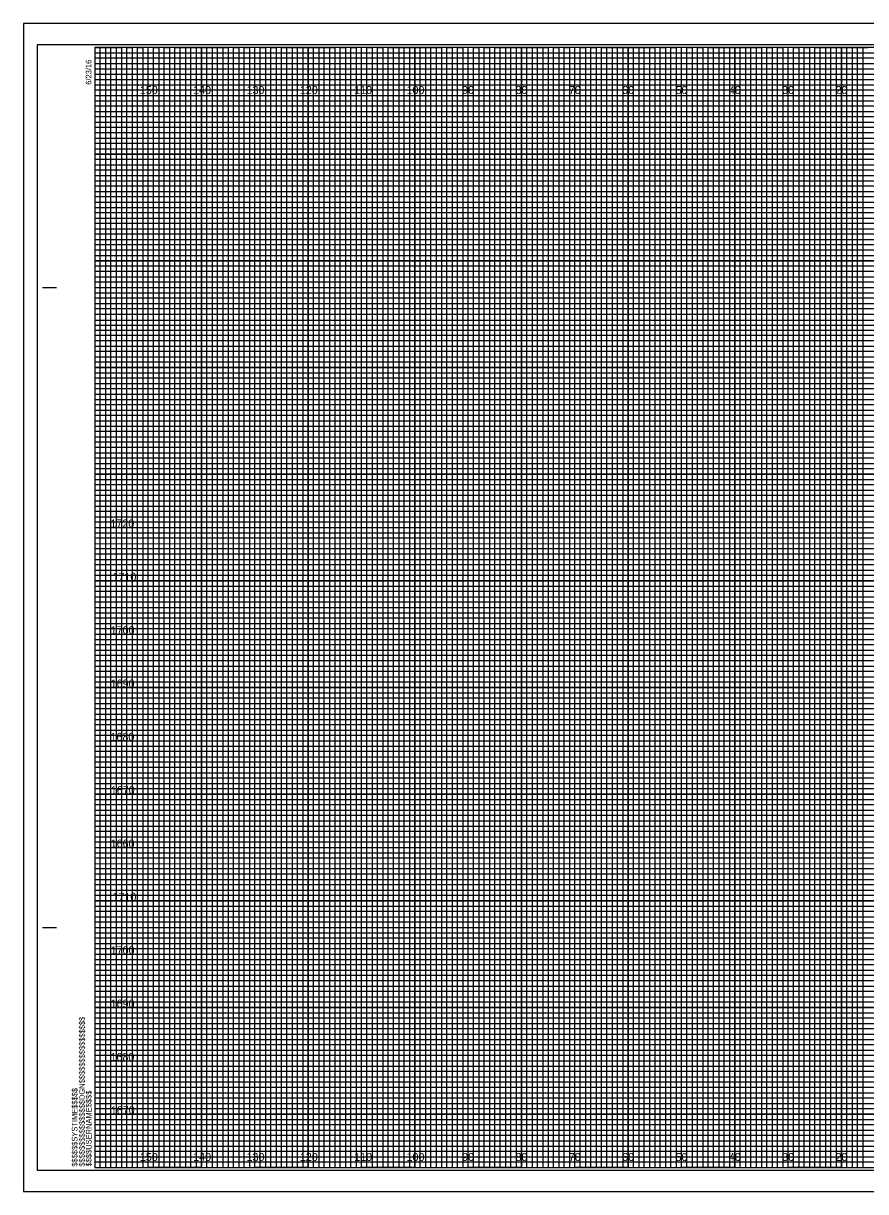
# Model space of a CAD drawing. Extents: x 656 to 993, y -2 to 2857.
# Drawn here: x 656.3 to 814.2, y -1.7 to 217.3 of the extents above; entities that cross this region are included whole.
import ezdxf

# ---------------------------------------------------------------- set-up
doc = ezdxf.new("R2010")
doc.units = 0
for name, color, linetype in [('Prop RDY Alternate Text Blue', 7, 'Continuous'), ('Prop Retaining Wall', 7, 'Continuous'), ('Prop SS Cut Line', 7, 'Continuous'), ('Prop SS Fill Line', 7, 'Continuous'), ('Prop SS Transition Line', 7, 'Continuous'), ('Raster_Level_0', 7, 'Continuous'), ('Raster_Level_3', 7, 'Continuous'), ('Scratch_Level_3', 7, 'Continuous'), ('Scratch_Level_7', 7, 'Continuous'), ('Typical Guardrail CELL', 7, 'Continuous'), ('Typical Text Asphalt at Bridge Approach CELL', 7, 'Continuous')]:
    doc.layers.add(name, color=color, linetype=linetype)

msp = doc.modelspace()

# ---------------------------------------------------------------- linework, layer by layer
at = {"layer": 'Prop RDY Alternate Text Blue'}
for p, q in [((679.74, 2.8), (679.74, 212.8)), ((689.74, 2.8), (689.74, 212.8)), ((699.74, 2.8), (699.74, 212.8)), ((709.74, 2.8), (709.74, 212.8)), ((719.74, 2.8), (719.74, 212.8)), ((729.74, 2.8), (729.74, 212.8)), ((739.74, 2.8), (739.74, 212.8)), ((749.74, 2.8), (749.74, 212.8)), ((759.74, 2.8), (759.74, 212.8)), ((769.74, 2.8), (769.74, 212.8)), ((779.74, 2.8), (779.74, 212.8)), ((789.74, 2.8), (789.74, 212.8)), ((799.74, 2.8), (799.74, 212.8)), ((809.74, 2.8), (809.74, 212.8)), ((669.74, 202.8), (989.74, 202.8)), ((669.74, 192.8), (989.74, 192.8)), ((669.74, 182.8), (989.74, 182.8)), ((669.74, 172.8), (989.74, 172.8)), ((669.74, 162.8), (989.74, 162.8)), ((669.74, 152.8), (989.74, 152.8)), ((669.74, 142.8), (989.74, 142.8)), ((669.74, 132.8), (989.74, 132.8)), ((669.74, 122.8), (989.74, 122.8)), ((669.74, 112.8), (989.74, 112.8)), ((669.74, 102.8), (989.74, 102.8)), ((669.74, 92.8), (989.74, 92.8)), ((669.74, 82.8), (989.74, 82.8)), ((669.74, 72.8), (989.74, 72.8)), ((669.74, 62.8), (989.74, 62.8)), ((669.74, 52.8), (989.74, 52.8)), ((669.74, 42.8), (989.74, 42.8)), ((669.74, 32.8), (989.74, 32.8)), ((669.74, 22.8), (989.74, 22.8)), ((669.74, 12.8), (989.74, 12.8))]:
    msp.add_line(p, q, dxfattribs=at)
at = {"layer": 'Prop Retaining Wall'}
for p, q in [((659.94, 167.8), (662.44, 167.8)), ((660.04, 167.8), (662.54, 167.8)), ((659.94, 47.8), (662.44, 47.8)), ((660.04, 47.8), (662.54, 47.8)), ((669.74, 2.8), (669.74, 2.8)), ((669.74, 2.8), (669.74, 2.8)), ((669.74, 2.8), (669.74, 2.8)), ((669.74, 2.8), (669.74, 2.8)), ((669.74, 2.8), (669.74, 2.8)), ((669.74, 2.8), (669.74, 2.8)), ((669.74, 2.8), (669.74, 2.8))]:
    msp.add_line(p, q, dxfattribs=at)
msp.add_lwpolyline([(989.74, 212.8), (669.74, 212.8), (669.74, 2.8), (989.74, 2.8)], close=True, dxfattribs=at)
at = {"layer": 'Prop SS Cut Line'}
for points in [[(669.74, 212.8), (674.74, 212.8), (674.74, 2.8), (684.74, 2.8), (684.74, 212.8), (694.74, 212.8), (694.74, 2.8), (704.74, 2.8), (704.74, 212.8), (714.74, 212.8), (714.74, 2.8), (724.74, 2.8), (724.74, 212.8), (734.74, 212.8), (734.74, 2.8), (744.74, 2.8), (744.74, 212.8), (754.74, 212.8), (754.74, 2.8), (764.74, 2.8), (764.74, 212.8), (774.74, 212.8), (774.74, 2.8), (784.74, 2.8), (784.74, 212.8), (794.74, 212.8), (794.74, 2.8), (804.74, 2.8), (804.74, 212.8), (814.74, 212.8)], [(669.74, 207.8), (944.74, 207.8)], [(669.74, 187.8), (989.74, 187.8), (989.74, 197.8), (669.74, 197.8)], [(669.74, 167.8), (989.74, 167.8), (989.74, 177.8), (669.74, 177.8)], [(669.74, 147.8), (989.74, 147.8), (989.74, 157.8), (669.74, 157.8)], [(669.74, 127.8), (989.74, 127.8), (989.74, 137.8), (669.74, 137.8)], [(669.74, 107.8), (989.74, 107.8), (989.74, 117.8), (669.74, 117.8)], [(669.74, 87.8), (989.74, 87.8), (989.74, 97.8), (669.74, 97.8)], [(669.74, 67.8), (989.74, 67.8), (989.74, 77.8), (669.74, 77.8)], [(669.74, 47.8), (989.74, 47.8), (989.74, 57.8), (669.74, 57.8)], [(669.74, 27.8), (989.74, 27.8), (989.74, 37.8), (669.74, 37.8)], [(669.74, 7.8), (989.74, 7.8), (989.74, 17.8), (669.74, 17.8)]]:
    msp.add_lwpolyline(points, dxfattribs=at)
at = {"layer": 'Prop SS Fill Line'}
for p, q in [((679.74, 212.8), (669.74, 212.8)), ((679.74, 2.8), (679.74, 212.8)), ((699.74, 212.8), (689.74, 212.8)), ((689.74, 212.8), (689.74, 2.8)), ((699.74, 2.8), (699.74, 212.8)), ((719.74, 212.8), (709.74, 212.8)), ((709.74, 212.8), (709.74, 2.8)), ((719.74, 2.8), (719.74, 212.8)), ((739.74, 212.8), (729.74, 212.8)), ((729.74, 212.8), (729.74, 2.8)), ((739.74, 2.8), (739.74, 212.8)), ((759.74, 212.8), (749.74, 212.8)), ((749.74, 212.8), (749.74, 2.8)), ((759.74, 2.8), (759.74, 212.8)), ((779.74, 212.8), (769.74, 212.8)), ((769.74, 212.8), (769.74, 2.8)), ((779.74, 2.8), (779.74, 212.8)), ((799.74, 212.8), (789.74, 212.8)), ((789.74, 212.8), (789.74, 2.8)), ((799.74, 2.8), (799.74, 212.8)), ((819.74, 212.8), (809.74, 212.8)), ((809.74, 212.8), (809.74, 2.8)), ((689.74, 2.8), (679.74, 2.8)), ((709.74, 2.8), (699.74, 2.8)), ((729.74, 2.8), (719.74, 2.8)), ((749.74, 2.8), (739.74, 2.8)), ((769.74, 2.8), (759.74, 2.8)), ((789.74, 2.8), (779.74, 2.8)), ((809.74, 2.8), (799.74, 2.8))]:
    msp.add_line(p, q, dxfattribs=at)
for points in [[(669.74, 202.8), (989.74, 202.8), (989.74, 192.8), (669.74, 192.8)], [(669.74, 182.8), (989.74, 182.8), (989.74, 172.8), (669.74, 172.8)], [(669.74, 162.8), (989.74, 162.8), (989.74, 152.8), (669.74, 152.8)], [(669.74, 142.8), (989.74, 142.8), (989.74, 132.8), (669.74, 132.8)], [(669.74, 122.8), (989.74, 122.8), (989.74, 112.8), (669.74, 112.8)], [(669.74, 102.8), (989.74, 102.8), (989.74, 92.8), (669.74, 92.8)], [(669.74, 82.8), (989.74, 82.8), (989.74, 72.8), (669.74, 72.8)], [(669.74, 62.8), (989.74, 62.8), (989.74, 52.8), (669.74, 52.8)], [(669.74, 42.8), (989.74, 42.8), (989.74, 32.8), (669.74, 32.8)], [(669.74, 22.8), (989.74, 22.8), (989.74, 12.8), (669.74, 12.8)]]:
    msp.add_lwpolyline(points, dxfattribs=at)
at = {"layer": 'Prop SS Transition Line'}
for p, q in [((669.74, 211.8), (929.74, 211.8)), ((929.74, 210.78), (669.74, 210.78)), ((669.74, 210.78), (669.74, 209.8)), ((669.74, 209.8), (929.74, 209.8)), ((929.74, 208.69), (669.74, 208.69)), ((669.74, 208.69), (669.74, 206.8)), ((669.74, 206.8), (989.74, 206.8))]:
    msp.add_line(p, q, dxfattribs=at)
for points in [[(669.74, 205.8), (939.74, 205.8), (989.74, 205.8), (989.74, 204.8), (669.74, 204.8)], [(669.74, 203.8), (989.74, 203.8), (989.74, 201.8), (669.74, 201.8)], [(669.74, 200.8), (989.74, 200.8), (989.74, 199.8), (669.74, 199.78)], [(669.74, 198.8), (989.74, 198.8), (989.74, 196.8), (669.74, 196.8)], [(669.74, 195.8), (989.74, 195.8), (989.74, 194.8), (669.74, 194.8)], [(669.74, 193.8), (989.74, 193.8), (989.74, 191.8), (669.74, 191.8)], [(669.74, 190.8), (989.74, 190.8), (989.74, 189.8), (669.74, 189.8)], [(669.74, 188.8), (989.74, 188.8), (989.74, 186.8), (669.74, 186.8)], [(669.74, 185.8), (989.74, 185.8), (989.74, 184.8), (669.74, 184.8)], [(669.74, 183.8), (989.74, 183.8), (989.74, 181.8), (669.74, 181.8)], [(669.74, 180.8), (989.74, 180.8), (989.74, 179.8), (669.74, 179.8)], [(669.74, 178.8), (989.74, 178.8), (989.74, 176.75), (989.74, 175.8), (989.74, 174.8), (669.74, 174.8)], [(669.74, 176.8), (989.74, 176.8), (989.74, 175.8), (669.74, 175.8)], [(669.74, 173.8), (989.74, 173.8), (989.74, 171.8), (669.74, 171.83)], [(669.74, 171.83), (989.74, 171.8), (989.74, 170.8), (669.74, 170.8)], [(669.74, 169.8), (989.74, 169.8), (989.74, 168.8), (669.74, 168.8)], [(669.74, 166.8), (989.74, 166.8), (989.74, 165.8), (669.74, 165.8)], [(669.74, 164.8), (989.74, 164.8), (989.74, 163.8), (669.74, 163.8)], [(669.67, 161.69), (989.74, 161.69), (989.74, 160.68), (669.67, 160.68)], [(669.74, 159.8), (989.74, 159.8), (989.74, 158.8), (669.74, 158.8)], [(669.74, 156.8), (989.74, 156.8), (989.74, 155.8), (669.74, 155.8)], [(669.74, 154.8), (989.74, 154.8), (989.74, 153.8), (669.74, 153.8)], [(669.74, 151.8), (989.74, 151.8), (989.74, 150.8), (669.74, 150.8)], [(669.74, 149.8), (989.74, 149.8), (989.74, 148.8), (669.74, 148.8)], [(669.74, 146.8), (989.74, 146.8), (989.74, 145.8), (669.74, 145.8)], [(669.74, 144.8), (989.74, 144.8), (989.74, 143.8), (669.74, 143.8)], [(669.74, 141.8), (989.74, 141.8), (989.73, 140.78), (669.74, 140.8)], [(669.74, 139.8), (989.74, 139.8), (989.74, 138.8), (669.74, 138.8)], [(669.74, 136.8), (989.74, 136.8), (989.74, 135.8), (669.74, 135.8)], [(669.74, 134.8), (989.74, 134.8), (989.74, 133.8), (669.74, 133.8)], [(669.74, 131.8), (989.74, 131.8), (989.74, 130.8), (669.74, 130.8)], [(669.74, 129.8), (989.74, 129.8), (989.74, 128.8), (669.74, 128.8)], [(669.74, 126.8), (989.74, 126.8), (989.74, 125.8), (669.74, 125.8)], [(669.74, 124.8), (989.74, 124.8), (989.74, 123.8), (669.74, 123.8)], [(669.74, 121.8), (989.74, 121.8), (989.74, 120.8), (669.74, 120.8)], [(669.74, 119.79), (989.81, 119.71), (989.74, 118.8), (669.74, 118.8)], [(669.74, 116.8), (989.74, 116.8), (989.74, 115.8), (669.74, 115.8)], [(669.74, 114.8), (989.74, 114.8), (989.74, 113.8), (669.74, 113.8)], [(669.74, 111.8), (989.74, 111.8), (989.74, 110.8), (669.74, 110.8)], [(669.74, 109.8), (989.74, 109.8), (989.74, 108.8), (669.74, 108.8)], [(669.74, 106.8), (989.74, 106.8), (989.74, 105.8), (669.74, 105.8)], [(669.74, 104.8), (989.74, 104.8), (989.74, 103.8), (669.74, 103.8)], [(669.74, 101.8), (989.74, 101.8), (989.74, 100.8), (669.74, 100.8)], [(669.74, 99.8), (989.74, 99.8), (989.74, 98.8), (669.74, 98.8)], [(669.74, 96.8), (989.74, 96.8), (989.74, 95.8), (669.74, 95.8)], [(669.74, 94.8), (989.74, 94.8), (989.74, 93.8), (669.74, 93.8)], [(669.74, 91.8), (989.74, 91.8), (989.74, 90.8), (669.74, 90.8)], [(669.74, 89.8), (989.74, 89.8), (989.74, 88.8), (669.74, 88.8)], [(669.74, 86.8), (989.74, 86.8), (989.74, 85.8), (669.74, 85.8)], [(669.74, 84.8), (989.74, 84.8), (989.74, 83.8), (669.74, 83.8)], [(669.74, 81.8), (989.74, 81.8), (989.73, 80.78), (669.74, 80.8)], [(669.74, 79.8), (989.74, 79.8), (989.74, 78.8), (669.74, 78.8)], [(669.74, 76.8), (989.74, 76.8), (989.74, 75.8), (669.74, 75.8)], [(669.74, 74.8), (989.74, 74.8), (989.74, 73.8), (669.74, 73.8)], [(669.74, 71.8), (989.74, 71.8), (989.74, 70.8), (669.74, 70.8)], [(669.74, 69.8), (989.74, 69.8), (989.74, 68.8), (669.74, 68.8)], [(669.74, 66.8), (989.74, 66.8), (989.74, 65.8), (669.74, 65.8)], [(669.74, 64.8), (989.74, 64.8), (989.74, 63.8), (669.74, 63.8)], [(669.74, 61.8), (989.74, 61.8), (989.74, 60.8), (669.74, 60.8)], [(669.74, 59.79), (989.81, 59.71), (989.74, 58.8), (669.74, 58.8)], [(669.74, 56.8), (989.74, 56.8), (989.74, 55.8), (669.74, 55.8)], [(669.74, 54.8), (989.74, 54.8), (989.74, 53.8), (669.74, 53.8)], [(669.74, 51.8), (989.74, 51.8), (989.74, 50.8), (669.74, 50.8)], [(669.74, 49.8), (989.74, 49.8), (989.74, 48.8), (669.74, 48.8)], [(669.74, 46.8), (989.74, 46.8), (989.74, 45.8), (669.74, 45.8)], [(669.74, 44.8), (989.74, 44.8), (989.74, 43.8), (669.74, 43.8)], [(669.74, 41.8), (989.74, 41.8), (989.74, 40.8), (669.74, 40.8)], [(669.74, 39.8), (989.74, 39.8), (989.74, 38.8), (669.74, 38.8)], [(669.74, 36.8), (989.74, 36.8), (989.74, 35.8), (669.74, 35.8)], [(669.74, 34.8), (989.74, 34.8), (989.74, 33.8), (669.74, 33.8)], [(669.74, 31.8), (989.74, 31.8), (989.74, 30.8), (669.74, 30.8)], [(669.74, 29.8), (989.74, 29.8), (989.74, 28.8), (669.74, 28.8)], [(669.74, 26.8), (989.74, 26.8), (989.74, 25.8), (669.74, 25.8)], [(669.74, 24.8), (989.74, 24.8), (989.74, 23.8), (669.74, 23.8)], [(669.74, 21.8), (989.74, 21.8), (989.74, 20.8), (669.74, 20.8)], [(669.74, 19.8), (989.74, 19.8), (989.74, 18.8), (669.74, 18.8)], [(669.74, 16.8), (989.74, 16.8), (989.74, 15.8), (669.74, 15.8)], [(669.74, 14.8), (989.74, 14.8), (989.74, 13.8), (669.74, 13.8)], [(669.74, 11.8), (989.74, 11.8), (989.74, 10.8), (669.74, 10.8)], [(669.74, 9.8), (989.74, 9.8), (989.74, 8.8), (669.74, 8.8)], [(669.74, 6.8), (989.74, 6.8), (989.74, 5.8), (669.74, 5.8)], [(669.74, 4.8), (989.74, 4.8), (989.74, 3.8), (669.74, 3.8)]]:
    msp.add_lwpolyline(points, dxfattribs=at)
at = {"layer": 'Raster_Level_3'}
for points in [[(669.74, 2.8), (670.74, 2.8), (670.74, 212.8), (671.74, 212.8), (671.74, 2.8)], [(671.74, 2.8), (672.74, 2.8), (672.74, 212.8), (673.74, 212.8), (673.74, 2.8)], [(674.74, 2.8), (675.74, 2.8), (675.74, 212.8), (676.74, 212.8), (676.74, 2.8)], [(676.74, 2.8), (677.74, 2.8), (677.74, 212.8), (678.74, 212.8), (678.74, 2.8)], [(679.74, 2.8), (680.74, 2.8), (680.74, 212.8), (681.74, 212.8), (681.74, 2.8)], [(681.74, 2.8), (682.74, 2.8), (682.74, 212.8), (683.74, 212.8), (683.74, 2.8)], [(684.74, 2.8), (685.74, 2.8), (685.74, 212.8), (686.74, 212.8), (686.74, 2.8)], [(686.74, 2.8), (687.74, 2.8), (687.74, 212.8), (688.74, 212.8), (688.74, 2.8)], [(689.74, 2.8), (690.74, 2.8), (690.74, 212.8), (691.74, 212.8), (691.74, 2.8)], [(691.74, 2.8), (692.74, 2.8), (692.74, 212.8), (693.74, 212.8), (693.74, 2.8)], [(694.74, 2.8), (695.74, 2.8), (695.74, 212.8), (696.74, 212.8), (696.74, 2.8)], [(696.74, 2.8), (697.74, 2.8), (697.74, 212.8), (698.74, 212.8), (698.74, 2.8)], [(699.74, 2.8), (700.74, 2.8), (700.74, 212.8), (701.74, 212.8), (701.74, 2.8)], [(701.74, 2.8), (702.74, 2.8), (702.74, 212.8), (703.74, 212.8), (703.74, 2.8)], [(704.74, 2.8), (705.74, 2.8), (705.74, 212.8), (706.74, 212.8), (706.74, 2.8)], [(706.74, 2.8), (707.74, 2.8), (707.74, 212.8), (708.74, 212.8), (708.74, 2.8)], [(709.74, 2.8), (710.74, 2.8), (710.74, 212.8), (711.74, 212.8), (711.74, 2.8)], [(711.74, 2.8), (712.74, 2.8), (712.74, 212.8), (713.74, 212.8), (713.74, 2.8)], [(714.74, 2.8), (715.74, 2.8), (715.74, 212.8), (716.74, 212.8), (716.74, 2.8)], [(716.74, 2.8), (717.74, 2.8), (717.74, 212.8), (718.74, 212.8), (718.74, 2.8)], [(719.74, 2.8), (720.74, 2.8), (720.74, 212.8), (721.74, 212.8), (721.74, 2.8)], [(721.74, 2.8), (722.74, 2.8), (722.74, 212.8), (723.74, 212.8), (723.74, 2.8)], [(724.74, 2.8), (725.74, 2.8), (725.74, 212.8), (726.74, 212.8), (726.74, 2.8)], [(726.74, 2.8), (727.74, 2.8), (727.74, 212.8), (728.74, 212.8), (728.74, 2.8)], [(729.74, 2.8), (730.74, 2.8), (730.74, 212.8), (731.74, 212.8), (731.74, 2.8)], [(731.74, 2.8), (732.74, 2.8), (732.74, 212.8), (733.74, 212.8), (733.74, 2.8)], [(734.74, 2.8), (735.74, 2.8), (735.74, 212.8), (736.74, 212.8), (736.74, 2.8)], [(736.74, 2.8), (737.74, 2.8), (737.74, 212.8), (738.74, 212.8), (738.74, 2.8)], [(739.74, 2.8), (740.74, 2.8), (740.74, 212.8), (741.74, 212.8), (741.74, 2.8)], [(741.74, 2.8), (742.74, 2.8), (742.74, 212.8), (743.74, 212.8), (743.74, 2.8)], [(744.74, 2.8), (745.74, 2.8), (745.74, 212.8), (746.74, 212.8), (746.74, 2.8)], [(746.74, 2.8), (747.74, 2.8), (747.74, 212.8), (748.74, 212.8), (748.74, 2.8)], [(749.74, 2.8), (750.74, 2.8), (750.74, 212.8), (751.74, 212.8), (751.74, 2.8)], [(751.74, 2.8), (752.74, 2.8), (752.74, 212.8), (753.74, 212.8), (753.74, 2.8)], [(754.74, 2.8), (755.74, 2.8), (755.74, 212.8), (756.74, 212.8), (756.74, 2.8)], [(756.74, 2.8), (757.74, 2.8), (757.74, 212.8), (758.74, 212.8), (758.74, 2.8)], [(759.74, 2.8), (760.74, 2.8), (760.74, 212.8), (761.74, 212.8), (761.74, 2.8)], [(761.74, 2.8), (762.74, 2.8), (762.74, 212.8), (763.74, 212.8), (763.74, 2.8)], [(764.74, 2.8), (765.74, 2.8), (765.74, 212.8), (766.74, 212.8), (766.74, 2.8)], [(766.74, 2.8), (767.74, 2.8), (767.74, 212.8), (768.74, 212.8), (768.74, 2.8)], [(769.74, 2.8), (770.74, 2.8), (770.74, 212.8), (771.74, 212.8), (771.74, 2.8)], [(771.74, 2.8), (772.74, 2.8), (772.74, 212.8), (773.74, 212.8), (773.74, 2.8)], [(774.74, 2.8), (775.74, 2.8), (775.74, 212.8), (776.74, 212.8), (776.74, 2.8)], [(776.74, 2.8), (777.74, 2.8), (777.74, 212.8), (778.74, 212.8), (778.74, 2.8)], [(779.74, 2.8), (780.74, 2.8), (780.74, 212.8), (781.74, 212.8), (781.74, 2.8)], [(781.74, 2.8), (782.74, 2.8), (782.74, 212.8), (783.74, 212.8), (783.74, 2.8)], [(784.74, 2.8), (785.74, 2.8), (785.74, 212.8), (786.74, 212.8), (786.74, 2.8)], [(786.74, 2.8), (787.74, 2.8), (787.74, 212.8), (788.74, 212.8), (788.74, 2.8)], [(789.74, 2.8), (790.74, 2.8), (790.74, 212.8), (791.74, 212.8), (791.74, 2.8)], [(791.74, 2.8), (792.74, 2.8), (792.74, 212.8), (793.74, 212.8), (793.74, 2.8)], [(794.74, 2.8), (795.74, 2.8), (795.74, 212.8), (796.74, 212.8), (796.74, 2.8)], [(796.74, 2.8), (797.74, 2.8), (797.74, 212.8), (798.74, 212.8), (798.74, 2.8)], [(799.74, 2.8), (800.74, 2.8), (800.74, 212.8), (801.74, 212.8), (801.74, 2.8)], [(801.74, 2.8), (802.74, 2.8), (802.74, 212.8), (803.74, 212.8), (803.74, 2.8)], [(804.74, 2.8), (805.74, 2.8), (805.74, 212.8), (806.74, 212.8), (806.74, 2.8)], [(806.74, 2.8), (807.74, 2.8), (807.74, 212.8), (808.74, 212.8), (808.74, 2.8)], [(809.74, 2.8), (810.74, 2.8), (810.74, 212.8), (811.74, 212.8), (811.74, 2.8)], [(811.74, 2.8), (812.74, 2.8), (812.74, 212.8), (813.74, 212.8), (813.74, 2.8)]]:
    msp.add_lwpolyline(points, dxfattribs=at)
at = {"layer": 'Scratch_Level_7'}
msp.add_lwpolyline([(656.34, -1.7), (993.04, -1.7), (993.04, 217.3), (656.34, 217.3)], close=True, dxfattribs=at)
at = {"layer": 'Typical Guardrail CELL'}
msp.add_lwpolyline([(658.94, 2.3), (992.14, 2.3), (992.14, 213.3), (658.94, 213.3)], close=True, dxfattribs=at)
at = {"layer": 'Typical Text Asphalt at Bridge Approach CELL'}
for p, q in [((993.04, 217.3), (656.34, 217.3)), ((656.34, 217.3), (656.34, -1.7)), ((656.34, -1.7), (993.04, -1.7))]:
    msp.add_line(p, q, dxfattribs=at)

# ---------------------------------------------------------------- texts
at = {"layer": 'Prop Retaining Wall'}
for s, p in [('6/23/16', (669.09, 205.8)), ('$$$$$$$$$$$$$$$$DGN$$$$$$$$$$$$$$$$', (667.86, 2.98)), ('$$$$$$SYSTIME$$$$$', (666.48, 2.98)), ('$$$$USERNAME$$$$', (669.12, 3.03))]:
    msp.add_text(s, height=1.05, rotation=90, dxfattribs=at).set_placement(p)
at = {"layer": 'Raster_Level_0'}
for s, p in [('150', (678.18, 204.05)), ('140', (688.18, 204.05)), ('130', (698.18, 204.05)), ('120', (708.18, 204.05)), ('110', (718.36, 204.05)), ('100', (728.18, 204.05)), ('90', (738.6, 204.05)), ('80', (748.6, 204.05)), ('70', (758.6, 204.05)), ('60', (768.6, 204.05)), ('50', (778.6, 204.05)), ('40', (788.6, 204.05)), ('30', (798.6, 204.05)), ('20', (808.6, 204.05)), ('150', (678.18, 4.05)), ('140', (688.18, 4.05)), ('130', (698.18, 4.05)), ('120', (708.18, 4.05)), ('110', (718.36, 4.05)), ('100', (728.18, 4.05)), ('90', (738.6, 4.05)), ('80', (748.6, 4.05)), ('70', (758.6, 4.05)), ('60', (768.6, 4.05)), ('50', (778.6, 4.05)), ('40', (788.6, 4.05)), ('30', (798.6, 4.05)), ('20', (808.6, 4.05))]:
    msp.add_text(s, height=1.5, dxfattribs=at).set_placement(p)
at = {"layer": 'Scratch_Level_3'}
for s, p in [('1720', (672.67, 122.8)), ('1710', (673.05, 112.8)), ('1700', (672.72, 102.8)), ('1690', (672.71, 92.8)), ('1680', (672.68, 82.8)), ('1670', (672.74, 72.8)), ('1660', (672.71, 62.8)), ('1710', (673.05, 52.8)), ('1700', (672.72, 42.8)), ('1690', (672.71, 32.8)), ('1680', (672.68, 22.8)), ('1670', (672.74, 12.8))]:
    msp.add_text(s, height=1.5, dxfattribs=at).set_placement(p)

doc.saveas('drawing.dxf')
